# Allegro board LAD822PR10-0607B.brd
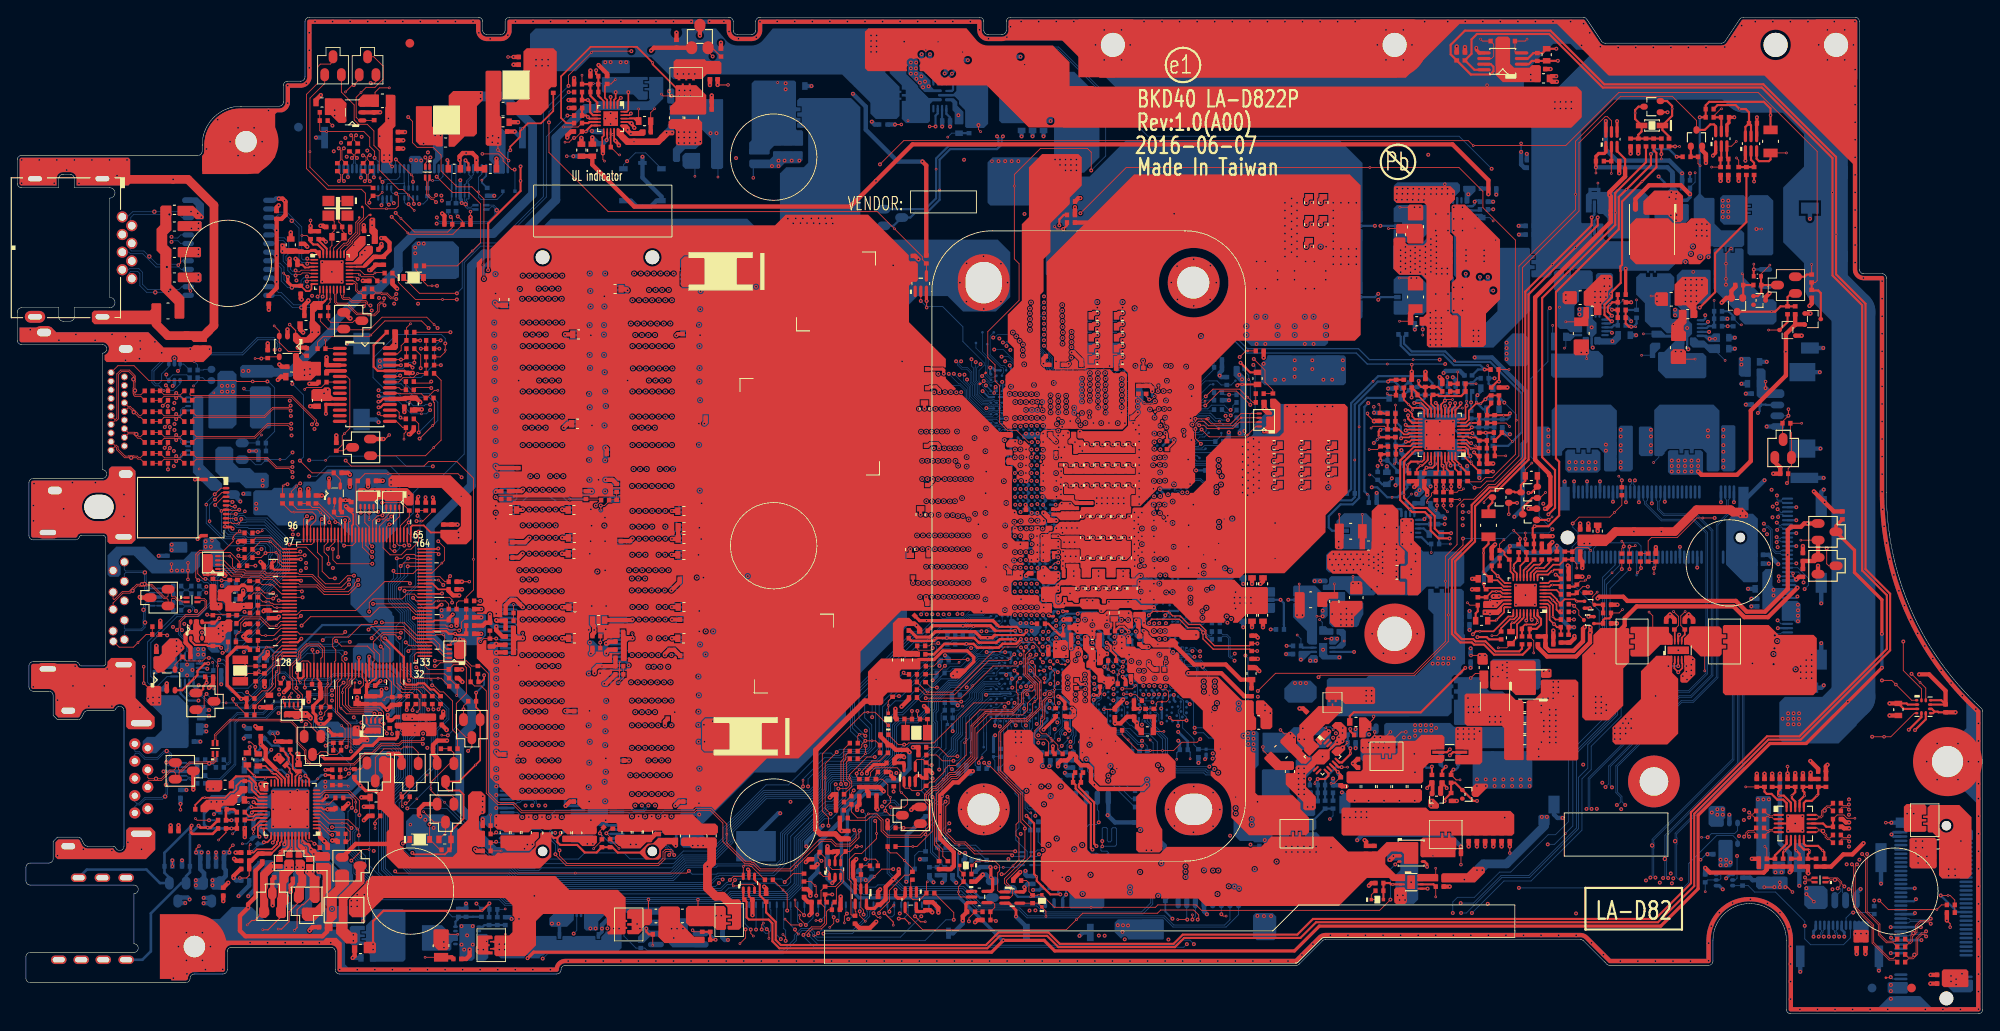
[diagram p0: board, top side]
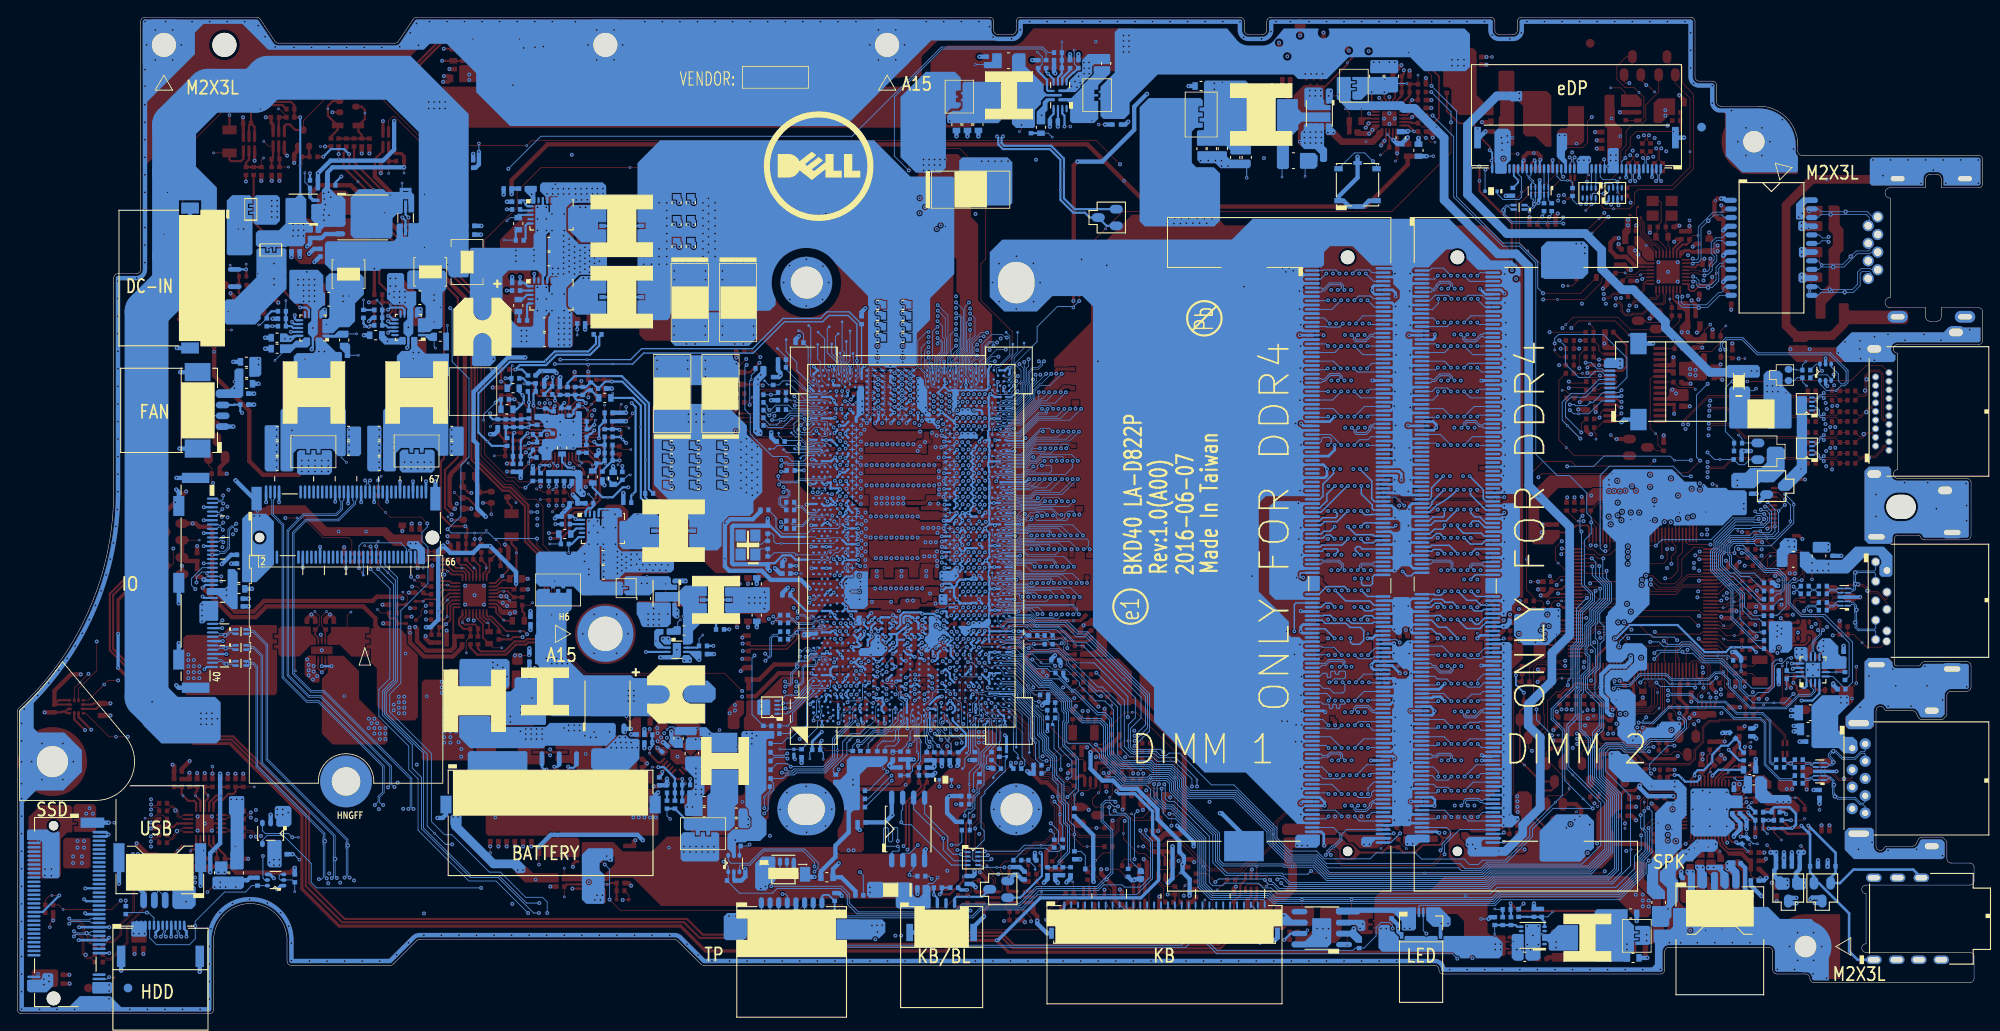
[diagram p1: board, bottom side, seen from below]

Outline 227.47 x 115.4 mm; copper layers: TOP, GND1, IN1, VCC, IN2, IN3, GND2, BOTTOM. Coordinates in mm from the lower left corner of the outline.

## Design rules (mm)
constraint set DEFAULT: min track width 0.102, pair gap 0.127
net group CLK_ITPXDP: nets CLK_ITPXDP_N CLK_ITPXDP_P
net group CLK_PCIE_LAN_P2_R: nets CLK_PCIE_LAN_N2_R CLK_PCIE_LAN_P2_R
net group CLK_PCIE_WLAN_P1_R: nets CLK_PCIE_WLAN_N1_R CLK_PCIE_WLAN_P1_R
net group DIFFPAIR2: nets SATA3_PRX_C_SSDTX_N2 SATA3_PRX_C_SSDTX_P2
net group DIFFPAIR3: nets SATA3_PTX_C_SSDRX_N2 SATA3_PTX_C_SSDRX_P2
net group DIFFPAIR4: nets PBAT_CHG_SMBCLK PBAT_CHG_SMBDAT
net group EDP_AUX_DP: nets EDP_AUX_DN EDP_AUX_DP
net group EDP_TX0_DP: nets EDP_TX0_DN EDP_TX0_DP
net group EDP_TX1_DP: nets EDP_TX1_DN EDP_TX1_DP
net group LAN_MIDI1+: nets LAN_MIDI1+ LAN_MIDI1-
net group LAN_MIDI3+: nets LAN_MIDI3+ LAN_MIDI3-
net group PCIE_PRX_C_LANTX_P6: nets PCIE_PRX_C_LANTX_N6 PCIE_PRX_C_LANTX_P6
net group PCIE_PRX_LANTX_P6: nets PCIE_PRX_LANTX_N6 PCIE_PRX_LANTX_P6
net group PCIE_PRX_WLANTX_P5: nets PCIE_PRX_WLANTX_N5 PCIE_PRX_WLANTX_P5
net group PCIE_PTX_C_LANRX_P6: nets PCIE_PTX_C_LANRX_N6 PCIE_PTX_C_LANRX_P6
net group PCIE_PTX_LANRX_P6: nets PCIE_PTX_LANRX_N6 PCIE_PTX_LANRX_P6
net group PCIE_PTX_WLANRX_P5: nets PCIE_PTX_WLANRX_N5 PCIE_PTX_WLANRX_P5
net group PCIE_RCOMPP: nets PCIE_RCOMPN PCIE_RCOMPP
net group SDOV_SCLK: nets SDVO_SCLK SDVO_SDATA
net group USB_PP1: nets USB_PN1 USB_PP1
net group AUDIO: nets AUD_HP_OUT_L_CN AUD_HP_OUT_R_CN HPOUT-L HPOUT-R LINE1-L LINE1-R LINE1-VREFO-L LINE1-VREFO-R LINE-IN-L LINE-IN-R
net group DDR_A_CLK: nets DDR_A_CLK0 DDR_A_CLK1 DDR_A_CLK#0 DDR_A_CLK#1
net group DDR_A_CMD: nets DDR_A_ACT# DDR_A_ALERT# DDR_A_BG0 DDR_A_BG1 DDR_A_BS0 DDR_A_BS1 DDR_A_CAS# DDR_A_MA0 DDR_A_MA1 DDR_A_MA2 DDR_A_MA3 DDR_A_MA4 DDR_A_MA5 DDR_A_MA6 DDR_A_MA7 DDR_A_MA8 DDR_A_MA9 DDR_A_MA10 DDR_A_MA11 DDR_A_MA12 DDR_A_MA13 DDR_A_PAR DDR_A_RAS# DDR_A_WE#
net group DDR_A_CTL: nets DDR_A_CKE0 DDR_A_CKE1 DDR_A_CS#0 DDR_A_CS#1 DDR_A_ODT0 DDR_A_ODT1
net group DDR_A_D0: nets DDR_A_D0 DDR_A_D1 DDR_A_D2 DDR_A_D3 DDR_A_D4 DDR_A_D5 DDR_A_D6 DDR_A_D7 DDR_A_DQS0 DDR_A_DQS#0
net group DDR_A_D1: nets DDR_A_D8 DDR_A_D9 DDR_A_D10 DDR_A_D11 DDR_A_D12 DDR_A_D13 DDR_A_D14 DDR_A_D15 DDR_A_DQS1 DDR_A_DQS#1
net group DDR_A_D2: nets DDR_A_D16 DDR_A_D17 DDR_A_D18 DDR_A_D19 DDR_A_D20 DDR_A_D21 DDR_A_D22 DDR_A_D23 DDR_A_DQS2 DDR_A_DQS#2
net group DDR_A_D3: nets DDR_A_D24 DDR_A_D25 DDR_A_D26 DDR_A_D27 DDR_A_D28 DDR_A_D29 DDR_A_D30 DDR_A_D31 DDR_A_DQS3 DDR_A_DQS#3
net group DDR_A_D4: nets DDR_A_D32 DDR_A_D33 DDR_A_D34 DDR_A_D35 DDR_A_D36 DDR_A_D37 DDR_A_D38 DDR_A_D39 DDR_A_DQS4 DDR_A_DQS#4
net group DDR_A_D5: nets DDR_A_D40 DDR_A_D41 DDR_A_D42 DDR_A_D43 DDR_A_D44 DDR_A_D45 DDR_A_D46 DDR_A_D47 DDR_A_DQS5 DDR_A_DQS#5
net group DDR_A_D6: nets DDR_A_D48 DDR_A_D49 DDR_A_D50 DDR_A_D51 DDR_A_D52 DDR_A_D53 DDR_A_D54 DDR_A_D55 DDR_A_DQS6 DDR_A_DQS#6
net group DDR_A_D7: nets DDR_A_D56 DDR_A_D57 DDR_A_D58 DDR_A_D59 DDR_A_D60 DDR_A_D61 DDR_A_D62 DDR_A_D63 DDR_A_DQS7 DDR_A_DQS#7
net group DDR_B_CLK: nets DDR_B_CLK0 DDR_B_CLK1 DDR_B_CLK#0 DDR_B_CLK#1
net group DDR_B_CMD: nets DDR_B_ACT# DDR_B_ALERT# DDR_B_BG0 DDR_B_BG1 DDR_B_BS0 DDR_B_BS1 DDR_B_CAS# DDR_B_MA0 DDR_B_MA1 DDR_B_MA2 DDR_B_MA3 DDR_B_MA4 DDR_B_MA5 DDR_B_MA6 DDR_B_MA7 DDR_B_MA8 DDR_B_MA9 DDR_B_MA10 DDR_B_MA11 DDR_B_MA12 DDR_B_MA13 DDR_B_PAR DDR_B_RAS# DDR_B_WE#
net group DDR_B_CTL: nets DDR_B_CKE0 DDR_B_CKE1 DDR_B_CS#0 DDR_B_CS#1 DDR_B_ODT0 DDR_B_ODT1
net group DDR_B_D0: nets DDR_B_D0 DDR_B_D1 DDR_B_D2 DDR_B_D3 DDR_B_D4 DDR_B_D5 DDR_B_D6 DDR_B_D7 DDR_B_DQS0 DDR_B_DQS#0
net group DDR_B_D1: nets DDR_B_D8 DDR_B_D9 DDR_B_D10 DDR_B_D11 DDR_B_D12 DDR_B_D13 DDR_B_D14 DDR_B_D15 DDR_B_DQS1 DDR_B_DQS#1
net group DDR_B_D2: nets DDR_B_D16 DDR_B_D17 DDR_B_D18 DDR_B_D19 DDR_B_D20 DDR_B_D21 DDR_B_D22 DDR_B_D23 DDR_B_DQS2 DDR_B_DQS#2
net group DDR_B_D3: nets DDR_B_D24 DDR_B_D25 DDR_B_D26 DDR_B_D27 DDR_B_D28 DDR_B_D29 DDR_B_D30 DDR_B_D31 DDR_B_DQS3 DDR_B_DQS#3
net group DDR_B_D4: nets DDR_B_D32 DDR_B_D33 DDR_B_D34 DDR_B_D35 DDR_B_D36 DDR_B_D37 DDR_B_D38 DDR_B_D39 DDR_B_DQS4 DDR_B_DQS#4
net group DDR_B_D5: nets DDR_B_D40 DDR_B_D41 DDR_B_D42 DDR_B_D43 DDR_B_D44 DDR_B_D45 DDR_B_D46 DDR_B_D47 DDR_B_DQS5 DDR_B_DQS#5
net group DDR_B_D6: nets DDR_B_D48 DDR_B_D49 DDR_B_D50 DDR_B_D51 DDR_B_D52 DDR_B_D53 DDR_B_D54 DDR_B_D55 DDR_B_DQS6 DDR_B_DQS#6
net group DDR_B_D7: nets DDR_B_D56 DDR_B_D57 DDR_B_D58 DDR_B_D59 DDR_B_D60 DDR_B_D61 DDR_B_D62 DDR_B_D63 DDR_B_DQS7 DDR_B_DQS#7
net group HDA: nets HDA_BIT_CLK HDA_CODEC_BITCLK HDA_CODEC_RST# HDA_CODEC_SDIN0 HDA_CODEC_SDOUT HDA_CODEC_SYNC HDA_RST# HDA_SDIN0 HDA_SDOUT HDA_SYNC ME_FWP_EC
net group KBO: nets KSI0 KSI1 KSI2 KSI3 KSI4 KSI5 KSI6 KSI7 KSO0 KSO1 KSO2 KSO3 KSO4 KSO5 KSO6 KSO7 KSO8 KSO9 KSO10 KSO11 KSO12 KSO13 KSO14 KSO15
net group PCIE: nets PCIE_PTX_C_WLANRX_N5 PCIE_PTX_C_WLANRX_P5 PCIE_WAKE#
net group S-8: nets LAN_WAKE# SERIRQ SYS_PWROK SYS_RESET#
net group SATA: nets SATA3_PRX_HDDTX_P0 SATA3_PRX_SSDTX_N2 SATA3_PRX_SSDTX_P2 SATA3_PTX_SSDRX_N2 SATA3_PTX_SSDRX_P2
net group SPI: nets EC_SPI_CLK EC_SPI_CS0# EC_SPI_MISO EC_SPI_MOSI EC_SPICLK_R EC_SPICS#_R PCH_SPI1_CLK_R PCH_SPI_CLK PCH_SPI_CLK_R PCH_SPI_CS2# PCH_SPI_CS2#_R PCH_SPI_CS#0 PCH_SPI_D0 PCH_SPI_D0_R PCH_SPI_D1 PCH_SPI_D1_R PCH_SPI_D2 PCH_SPI_D2_R PCH_SPI_D3 PCH_SPI_D3_R PCH_SPI_MISO PCH_SPI_MOSI XDP_SPI_IO2
net group SPK: nets INT-SPK-L+ INT-SPK-L- INT-SPK-R+ INT-SPK-R- MIC_IN_R RING2 RING2_R SLEEVE SPK_L1-_CONN SPK_L2+_CONN SPK_R1-_CONN SPK_R2+_CONN
net group USB_PP1_CHR: nets USB_PN1_CHR
nets with their own width: min track width 0.127; nets +TP_VDD
nets with their own width: min track width 0.152; nets VCC_GT_SENSE VCCSENSE VSA_SEN+ VSA_SEN- VSS_GT_SENSE VSSSENSE
nets with their own width: min track width 0.254; nets BAT1_LED# BAT2_LED# CFG_RCOMP CLK_SMB DAT_SMB EDP_COMP EN_1.0V_VCCST_ON KB_BL_CTRL# KB_LED_BL_DET KB_LED_DET_C KB_LED_PWM LDO_+1VALW N40605947 N41378522 N41825015 SM_RCOMP0 SM_RCOMP1 SM_RCOMP2
nets with their own width: min track width 0.305; nets CBN CBP CPU_POPIRCOMP CPVEE
nets with their own width: min track width 0.381; nets LDO3_CAP
nets with their own width: min track width 0.508; nets +1.0VS_VCCIO +1.0VS_VCCOPC +1.8V_AVDD +1.8V_PRIM +1.8VALWP +3V_SPI +3VALW +3VALW_PCH +3VS +5VALW +5VS +VCC_GT BST_+1VALW_R GND GNDA N28714793 N41866816
nets with their own width: min track width 0.762; nets +3.3V_LAN
nets with their own width: min track width 1.016; nets +0.6V_DDR_VTT +1.0V_PRIM +1.0V_VCCST +2.5V_MEM +2.5VP +3.3V_WLAN +DCBATOUT_LCD +TPAN_VDD LAN_GND MCT1 MCT2 MCT3 MCT4 N40740280
nets with their own width: min track width 1.27; nets 5V_HDD
nets with their own width: min track width 1.524; nets +0.6VSP +LAN_VDDREG
nets with their own width: min track width 2.032; nets +5V_PVDD +5VS_HDMI +LCDVDD_LCD +USB30_VCCB +USB30_VCCC
nets with their own width: min track width 2.54; nets +USB30_VCCA
nets with their own width: min track width 4.064; nets +3VS_SSD

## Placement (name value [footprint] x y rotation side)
C229  VALUE}  [C_0402]  29.11 82.23 90 top
C2403  VALUE}  [C_0402]  25.48 50.24 270 top
C2503  VALUE}  [C_0402]  211.23 57.26 90 top
C2601  VALUE}  [C_0603]  175.92 108.33 0 top
C2602  VALUE}  [C_0402]  175.91 109.41 0 top
C2603  VALUE}  [C_0402]  201.65 71.81 180 bottom
C2604  VALUE}  [C_0402]  200.74 70.54 0 bottom
C2606  VALUE}  [C_0603]  177 110.36 90 top
C2607  VALUE}  [C_0402]  175.92 110.35 90 top
C2608  VALUE}  [C_0402]  167.54 110.41 90 top
C2609  VALUE}  [C_0402]  166.59 110.41 90 top
C2612  VALUE}  [C_0402]  123.1 26.79 180 top
C2613  VALUE}  [C_0402]  47.15 33.46 90 top
C2715  VALUE}  [C_0402]  26.84 17.71 180 top
C3013  VALUE}  [C_0402]  32.17 74.93 180 top
C3015  VALUE}  [C_0402]  34.14 80.83 180 top
C3017  VALUE}  [C_0402]  33.49 77.99 270 top
C3403  VALUE}  [C_0402]  21.06 48.64 180 bottom
C3404  VALUE}  [C_0402]  21.06 49.53 180 bottom
C3405  VALUE}  [C_0402]  23.9 29.42 180 bottom
C3406  VALUE}  [C_0402]  23.9 28.53 180 bottom
C3504  VALUE}  [C_0402]  16.09 41 90 top
C3507  VALUE}  [C_0402]  19.52 31.52 0 bottom
C3508  VALUE}  [C_0402]  17.36 52.12 90 bottom
C3510  VALUE}  [C_0402]  197.21 18.47 180 bottom
C3512  VALUE}  [C_0805]  18.95 52.17 90 bottom
C3513  VALUE}  [C_0805]  19.37 32.95 0 bottom
C5201  VALUE}  [C_0402]  43.13 100.2 0 top
C5202  VALUE}  [C_0402]  55.77 102.17 0 top
C5203  VALUE}  [C_0402]  38.45 100.78 270 top
C5204  VALUE}  [C_0603]  35.97 105.53 180 top
C5205  VALUE}  [C_0603]  56.92 103.25 180 top
C5206  VALUE}  [C_0402]  44.05 101.15 180 top
C5207  VALUE}  [C_0603]  51.27 97.85 180 top
C5209  VALUE}  [C_0402]  40.03 98.5 270 top
C5210  VALUE}  [C_0402]  39.4 100.78 270 top
C5211  VALUE}  [C_0402]  37.05 98.5 270 top
C5212  VALUE}  [C_0402]  40.99 98.5 270 top
C5213  VALUE}  [C_0402]  38 98.5 270 top
C5224  VALUE}  [C_0603]  39.34 37.33 270 top
C5225  VALUE}  [C_0402]  28.6 40.27 90 top
C5226  VALUE}  [C_0402]  28.6 39.4 270 top
C5529  VALUE}  [C_0402]  223.12 4.5 180 top
C5530  VALUE}  [C_0402]  222.74 17.33 180 top
C5531  VALUE}  [C_0402]  223.12 3.49 180 top
C5532  VALUE}  [C_0603]  223 19.62 180 top
C5533  VALUE}  [C_0402]  222.74 18.22 180 top
C5801  VALUE}  [C_0402]  202.29 48.06 180 bottom
C5802  VALUE}  [C_0402]  202.29 47.18 180 bottom
C5803  VALUE}  [C_0402]  180.88 55.16 90 top
C5804  VALUE}  [C_0402]  201.12 52.13 0 bottom
C5805  VALUE}  [C_0603]  202.53 49.21 180 bottom
C5806  VALUE}  [C_0603]  182.91 55.18 90 top
C6201  VALUE}  [C_0402]  132.87 13.06 90 bottom
C6202  VALUE}  [C_0402]  122.38 14.6 0 bottom
C6204  VALUE}  [C_0402]  48.11 30.69 0 top
C6213  VALUE}  [C_0603]  201.64 72.96 180 bottom
C6214  VALUE}  [C_0603]  200.24 75.5 0 bottom
C6215  VALUE}  [C_0402]  212.88 8.52 270 top
C6216  VALUE}  [C_0805]  203.86 15.46 90 bottom
C6217  VALUE}  [C_0402]  213.9 8.52 270 top
C6218  VALUE}  [C_0603]  29.18 35.49 90 top
C6219  VALUE}  [C_0402]  43.13 102.1 0 top
C6220  VALUE}  [C_0402]  16.55 44.83 180 top
C6221  VALUE}  [C_0402]  181.83 55.16 90 top
C6223  VALUE}  [C_0402]  38 19.92 180 top
C6225  VALUE}  [C_0402]  92.84 12.94 180 top
C6226  VALUE}  [C_0402]  94.28 12.05 0 top
CA23  VALUE}  [C_0603]  24.88 24.76 0 top
CA24  VALUE}  [C_0402]  27.85 19.67 135 bottom
CA25  VALUE}  [C_0402]  28.1 24.12 270 bottom
CA29  VALUE}  [C_0402]  28.95 17.43 180 bottom
CA30  VALUE}  [C_0402]  30.66 15.79 180 top
CA31  VALUE}  [C_0402]  33.81 15.73 0 bottom
CA32  VALUE}  [C_0402]  32.81 15.6 180 top
CA33  VALUE}  [C_0402]  17.03 17.08 0 bottom
CA38  VALUE}  [C_0402]  23.92 17.08 180 bottom
CA39  VALUE}  [C_0402]  19.98 17.08 180 bottom
CA40  VALUE}  [C_0402]  21.17 17.08 0 bottom
CA51  VALUE}  [C_0402]  26.97 25.93 180 bottom
CA53  VALUE}  [C_0402]  37.71 10.32 270 bottom
CA54  VALUE}  [C_0402]  35.77 17.99 270 top
CA55  VALUE}  [C_0402]  36.8 10.32 270 bottom
CA56  VALUE}  [C_0402]  34.85 17.99 270 top
CA57  VALUE}  [C_0603]  42.23 25.05 180 top
CA58  VALUE}  [C_0402]  41.99 23.97 180 top
CA59  VALUE}  [C_0402]  28.98 23.21 90 bottom
CA60  VALUE}  [C_0402]  28.06 21.76 0 bottom
CA61  VALUE}  [C_0402]  26.84 16.76 180 top
CA62  VALUE}  [C_0402]  26.33 26.04 90 top
CA63  VALUE}  [C_0402]  25.92 18.66 0 top
CA64  VALUE}  [C_0402]  37.74 23.79 180 top
CA65  VALUE}  [C_0402]  37.37 26.47 90 top
CA67  VALUE}  [C_0603]  26.63 28.82 90 top
CA68  VALUE}  [C_0603]  27.9 28.69 90 top
CA69  VALUE}  [C_0402]  36.58 31.38 90 top
CA71  VALUE}  [C_0603]  27.2 27.03 180 bottom
CA74  VALUE}  [C_0603]  27.68 28.25 180 bottom
CA75  VALUE}  [C_0402]  23.92 17.98 180 bottom
CA76  VALUE}  [C_0402]  21.17 17.99 0 bottom
CC9  VALUE}  [C_0402]  129.3 22.16 0 bottom
CC21  VALUE}  [C_0402]  140.62 55.61 90 bottom
CC22  VALUE}  [C_0402]  140.62 52.97 270 bottom
CC23  VALUE}  [C_0402]  105.33 34.12 90 top
CC24  VALUE}  [C_0402]  98.9 16.77 270 bottom
CC25  VALUE}  [C_0402]  99.61 28.01 0 top
CC26  VALUE}  [C_0402]  102.68 34.13 180 top
CC27  VALUE}  [C_0402]  109.43 43.81 0 bottom
CC57  VALUE}  [C_0402]  103.66 86.85 90 top
CC58  VALUE}  [C_0402]  142.76 35.02 0 top
CC59  VALUE}  [C_0402]  157.06 18.52 90 top
CC93  VALUE}  [C_0402]  110.43 15.3 180 top
CC135  VALUE}  [C_0402]  139.17 46.16 180 bottom
CC136  VALUE}  [C_0402]  139.17 45.27 180 bottom
CC174  VALUE}  [C_0402]  114.84 50.21 90 top
CC175  VALUE}  [C_0402]  105.18 66.68 270 top
CC176  VALUE}  [C_0402]  105.31 60.31 90 top
CC177  VALUE}  [C_0402]  104.41 47.49 0 top
CC178  VALUE}  [C_0402]  103.66 51.44 270 top
CC179  VALUE}  [C_0402]  104.54 53.12 0 top
CC181  VALUE}  [C_0402]  119.8 50.02 270 top
CC182  VALUE}  [C_0402]  119.5 57.12 270 top
CC185  VALUE}  [C_0402]  118.28 51.01 180 top
CC186  VALUE}  [C_0402]  172.74 20.91 270 top
CC194  VALUE}  [C_0402]  114.81 63.05 90 top
CC195  VALUE}  [C_0402]  130.34 46.15 90 top
CC199  VALUE}  [C_0402]  138 48.47 0 bottom
CC202  VALUE}  [C_0402]  129.46 46.15 90 top
CC203  VALUE}  [C_0402]  129.25 34.4 90 top
CC204  VALUE}  [C_0402]  118.58 30.27 270 bottom
CC205  VALUE}  [C_0402]  123.94 46.21 90 top
CC206  VALUE}  [C_0402]  128.01 46.34 90 top
CC207  VALUE}  [C_0402]  91.98 16.99 90 top
CC210  VALUE}  [C_0805]  142.83 33.73 0 top
CC211  VALUE}  [C_0402]  128.68 42.17 90 top
CC212  VALUE}  [C_0402]  123.08 40.38 0 top
CC213  VALUE}  [C_0402]  107.8 40.95 180 bottom
CC214  VALUE}  [C_0402]  109.08 36.93 180 bottom
CC215  VALUE}  [C_0402]  121.05 43.86 0 top
CC216  VALUE}  [C_0402]  121.85 44.75 90 top
CC217  VALUE}  [C_0402]  142.76 35.91 0 top
CC218  VALUE}  [C_0402]  128.87 40.01 270 top
CC220  VALUE}  [C_0603]  142.84 38.69 90 top
CC221  VALUE}  [C_0402]  129.89 43.72 270 top
CC223  VALUE}  [C_0402]  120.25 41.65 180 top
CC224  VALUE}  [C_0402]  121.05 42.96 0 top
CC225  VALUE}  [C_0603]  125.12 42.79 180 top
CC226  VALUE}  [C_0603]  126.97 45.71 90 top
CC248  VALUE}  [C_0402]  171.78 20.91 270 top
CC249  VALUE}  [C_0402]  170.83 20.91 270 top
CC250  VALUE}  [C_0402]  169.88 20.91 270 top
CC251  VALUE}  [C_0402]  168.93 20.91 270 top
CC252  VALUE}  [C_0402]  167.97 20.91 270 top
CC253  VALUE}  [C_0402]  118.91 50.02 270 top
CC255  VALUE}  [C_0402]  105.31 75.57 270 top
CC256  VALUE}  [C_0402]  116.74 54.35 90 top
CC257  VALUE}  [C_0402]  114.84 65.01 90 top
CC258  VALUE}  [C_0402]  105.31 73.35 270 top
CC265  VALUE}  [C_0402]  91.06 14.43 270 top
CC266  VALUE}  [C_0402]  97.64 16.12 180 top
CC270  VALUE}  [C_0402]  98.52 25.24 0 top
CC271  VALUE}  [C_0402]  99.62 12.63 90 top
CC272  VALUE}  [C_0402]  122.34 33.59 180 top
CC273  VALUE}  [C_0402]  124.83 46.21 90 top
CC279  VALUE}  [C_0603]  101.82 40.25 90 top
CC280  VALUE}  [C_0603]  103.09 40.25 90 top
CC293  VALUE}  [C_0603]  103.34 54.48 270 top
CC294  VALUE}  [C_0603]  104.55 57.08 90 top
CC295  VALUE}  [C_0603]  104.99 69.34 90 top
CC296  VALUE}  [C_0402]  116.73 57.44 90 top
CC297  VALUE}  [C_0402]  119.47 47.23 90 top
CC1801  VALUE}  [C_0402]  125.25 40.64 270 top
CC1802  VALUE}  [C_0402]  108.26 36.04 180 bottom
CC1803  VALUE}  [C_0201]  108.23 33.5 180 bottom
CC1805  VALUE}  [C_0402]  50.88 38.87 180 top
CC1806  VALUE}  [C_0402]  105.18 26.4 90 top
CC1807  VALUE}  [C_0201]  137.59 30.63 270 bottom
CC1808  VALUE}  [C_0402]  138.51 71.05 0 bottom
CC1809  VALUE}  [C_0402]  143.34 70.8 0 top
CC1810  VALUE}  [C_0402]  32.73 59.1 90 top
CC1815  VALUE}  [C_0402]  139.17 44.25 180 bottom
CC1816  VALUE}  [C_0402]  139.17 43.37 180 bottom
CC1820  VALUE}  [C_0402]  105.12 12 90 top
CC1821  VALUE}  [C_0402]  110.9 16.45 270 bottom
CC1822  VALUE}  [C_0402]  110.85 11.81 180 top
CC1823  VALUE}  [C_0201]  112.98 30.36 270 bottom
CC1824  VALUE}  [C_0402]  121.5 94.06 0 top
CC1825  VALUE}  [C_0402]  127.18 73.79 90 top
CC1826  VALUE}  [C_0402]  128.13 69.01 0 top
CC1827  VALUE}  [C_0402]  122.23 68.02 270 top
CC1828  VALUE}  [C_0402]  119.54 68.02 270 top
CC1829  VALUE}  [C_0402]  118.13 76.14 0 top
CC1830  VALUE}  [C_0402]  119.43 74.24 90 top
CC1831  VALUE}  [C_0402]  121.03 74.24 90 top
CC1832  VALUE}  [C_0402]  123.14 74.24 90 top
CD1  VALUE}  [C_0402]  69.27 29.32 0 top
CD2  VALUE}  [C_0402]  67.31 64.83 0 top
CD3  VALUE}  [C_0402]  79.28 20.18 90 top
CD4  VALUE}  [C_0402]  65.88 20.3 90 top
CD5  VALUE}  [C_0603]  77.85 58.21 180 top
CD6  VALUE}  [C_0603]  56.39 58.34 0 top
CD7  VALUE}  [C_0603]  65.21 43.48 180 top
CD8  VALUE}  [C_0603]  65.15 53.26 180 top
CD9  VALUE}  [C_0603]  80.36 19.87 90 top
CD10  VALUE}  [C_0603]  63.53 20.25 90 top
CD11  VALUE}  [C_D3]  87.49 32.13 180 top
CD12  VALUE}  [C_0402]  74.2 20.81 90 top
CD13  VALUE}  [C_0603]  70.51 20.32 90 top
CD14  VALUE}  [C_0603]  58.96 20.27 90 top
CD15  VALUE}  [C_0603]  57.69 20.27 90 top
CD16  VALUE}  [C_0402]  76.2 20.14 90 top
CD17  VALUE}  [C_0603]  66.58 45.59 0 top
CD18  VALUE}  [C_0402]  70.15 43.11 180 top
CD19  VALUE}  [C_0402]  56.39 52.83 0 top
CD20  VALUE}  [C_0402]  76.19 34.16 180 top
CD21  VALUE}  [C_0402]  78.01 24.57 180 top
CD22  VALUE}  [C_0402]  77.64 41.46 180 top
CD23  VALUE}  [C_0603]  77.88 54.99 180 top
CD24  VALUE}  [C_0603]  65.15 58.34 180 top
CD25  VALUE}  [C_0603]  68.48 83.94 0 top
CD26  VALUE}  [C_0603]  65.2 55.1 180 top
CD27  VALUE}  [C_0603]  64.8 20.25 90 top
CD28  VALUE}  [C_0603]  77.28 19.86 90 top
CD29  VALUE}  [C_0402]  57.43 41.84 180 top
CD30  VALUE}  [C_0402]  66.77 20.3 90 top
CD31  VALUE}  [C_0402]  78.36 20.16 90 top
CD32  VALUE}  [C_0402]  60.04 20.75 90 top
CD33  VALUE}  [C_D3]  84.6 85.97 180 top
CD34  VALUE}  [C_0402]  75.28 20.11 90 top
CD35  VALUE}  [C_0603]  61.36 20.23 90 top
CD69  VALUE}  [C_0402]  56.01 59.6 90 top
CD70  VALUE}  [C_0603]  77.89 47.1 180 top
CD71  VALUE}  [C_0603]  65.56 68.32 180 top
CD72  VALUE}  [C_0603]  77.88 56.38 180 top
CD73  VALUE}  [C_0603]  65.69 78.67 180 top
CD74  VALUE}  [C_0402]  78.76 69.02 0 top
CD75  VALUE}  [C_0402]  68.91 54.73 0 top
CD76  VALUE}  [C_0402]  77.58 50.35 180 top
CD77  VALUE}  [C_0402]  65.4 35.05 180 top
CD78  VALUE}  [C_0402]  65.33 24.57 180 top
CD79  VALUE}  [C_0402]  57.28 30.03 180 top
CD80  VALUE}  [C_0402]  56.33 54.61 0 top
CD81  VALUE}  [C_0402]  77.64 45.65 180 top
CD82  VALUE}  [C_0402]  77.93 78.72 180 top
CD83  VALUE}  [C_0402]  57.99 62.28 90 top
CD84  VALUE}  [C_0603]  65.24 47.08 180 top
CD85  VALUE}  [C_0603]  77.85 53.13 180 top
CD86  VALUE}  [C_0603]  77.85 43.48 180 top
CD87  VALUE}  [C_0603]  56.35 83.43 270 top
CD88  VALUE}  [C_0603]  71.78 20.32 90 top
CD89  VALUE}  [C_0603]  56.42 20.27 90 top
CD90  VALUE}  [C_0603]  72.99 20.32 90 top
CD91  VALUE}  [C_0402]  65.81 59.61 90 top
CD92  VALUE}  [C_0402]  56.92 59.61 90 top
CE1  VALUE}  [C_0402]  76.29 111.87 90 top
CE2  VALUE}  [C_0402]  81.44 110.85 90 top
CE8  VALUE}  [C_0402]  51.96 46.86 0 top
CE62  VALUE}  [C_0402]  50.26 55.74 90 top
CE63  VALUE}  [C_0402]  49.3 56.65 270 top
CE64  VALUE}  [C_0402]  29.15 45.8 90 top
CE65  VALUE}  [C_0402]  40.41 36.78 270 top
CE66  VALUE}  [C_0402]  49.93 49.14 0 top
CE67  VALUE}  [C_0402]  29.45 51.72 180 top
CE68  VALUE}  [C_0402]  38.64 58.34 90 top
CE69  VALUE}  [C_0402]  49.93 45.59 0 top
CE70  VALUE}  [C_0402]  25.4 46.17 90 top
CE71  VALUE}  [C_0402]  41.37 36.78 270 top
CE72  VALUE}  [C_0402]  49.93 50.03 0 top
CE73  VALUE}  [C_0402]  27.85 43.24 180 top
CE74  VALUE}  [C_0402]  48.16 58.28 90 top
CE75  VALUE}  [C_0402]  51.96 44 0 top
CE76  VALUE}  [C_0402]  27.22 54.73 180 top
CE77  VALUE}  [C_0402]  127.03 34.34 90 top
CE79  VALUE}  [C_0402]  40.5 38.01 0 top
CE81  VALUE}  [C_0402]  22.55 48.19 0 top
CE82  VALUE}  [C_0402]  46.32 58.28 90 top
CE84  VALUE}  [C_0402]  31.4 38.29 180 top
CE85  VALUE}  [C_0402]  40.59 61.72 0 top
CE86  VALUE}  [C_0402]  36.62 62.64 0 top
CE87  VALUE}  [C_0402]  26.89 50.11 270 top
CE88  VALUE}  [C_0402]  27.85 47.3 180 top
CE89  VALUE}  [C_0603]  35.12 36.99 180 top
CE91  VALUE}  [C_0402]  43.4 36.67 270 top
CH100  VALUE}  [C_0402]  56.52 45.53 0 top
CH101  VALUE}  [C_0402]  69.23 40.25 0 top
CHD1  VALUE}  [C_0402]  217.58 8.64 0 top
CHD2  VALUE}  [C_0402]  217.58 7.75 0 top
CHD3  VALUE}  [C_0402]  217.58 6.87 0 top
CHD4  VALUE}  [C_0402]  217.58 5.98 0 top
CHO8  VALUE}  [C_0402]  16.53 68.6 0 top
CHO9  VALUE}  [C_0402]  16.53 71.04 0 top
CHO10  VALUE}  [C_0402]  16.53 66.16 0 top
CHO11  VALUE}  [C_0402]  16.53 63.75 0 top
CHR7  VALUE}  [C_0402]  20.25 63.75 180 top
CHR8  VALUE}  [C_0402]  20.25 64.89 180 top
CHR9  VALUE}  [C_0402]  20.25 66.16 180 top
CHR10  VALUE}  [C_0402]  20.25 67.3 180 top
CHR11  VALUE}  [C_0402]  20.25 71.05 180 top
CHR12  VALUE}  [C_0402]  20.25 72.13 180 top
CHR13  VALUE}  [C_0402]  20.25 68.57 180 top
CHR14  VALUE}  [C_0402]  20.25 69.72 180 top
CL1  VALUE}  [C_0402]  40.88 88.51 0 top
CL2  VALUE}  [C_0402]  42.41 87.65 270 top
CL3  VALUE}  [C_0402]  32.86 88.25 90 top
CL4  VALUE}  [C_0402]  41.47 87.65 270 top
CL5  VALUE}  [C_0603]  31.65 88.32 90 top
CL6  VALUE}  [C_0402]  32.8 84.3 270 top
CL7  VALUE}  [C_0402]  32.43 86.74 180 top
CL8  VALUE}  [C_0603]  34.13 79.75 180 top
CL9  VALUE}  [C_0402]  41.06 90.67 180 top
CL11  VALUE}  [C_0402]  34.14 81.78 180 top
CL12  VALUE}  [C_0402]  34.89 89.71 90 top
CL13  VALUE}  [C_0402]  40.15 83.05 0 top
CL14  VALUE}  [C_0402]  40.15 83.94 0 top
CL16  VALUE}  [C_0402]  37.61 91.12 0 top
CL17  VALUE}  [C_0402]  36.68 91.12 180 top
CL43  VALUE}  [C_1206]  18.76 81.39 180 top
CL44  VALUE}  [C_0402]  20.7 77.15 90 top
CL45  VALUE}  [C_0402]  21.61 77.15 90 top
CL46  VALUE}  [C_0402]  30.01 92.96 270 top
CLRP1  VALUE}  [SHORTPADS]  97.44 16.06 90 bottom
CN19  VALUE}  [C_0402]  223.17 35.82 270 top
CN20  VALUE}  [C_0603]  217.71 35.94 270 top
CS27  VALUE}  [C_0402]  202.48 17.05 180 top
CS30  VALUE}  [C_0402]  210.14 24.38 0 top
CS31  VALUE}  [C_0402]  210.14 20.7 0 top
CS32  VALUE}  [C_0402]  210.14 23.49 0 top
CS33  VALUE}  [C_0402]  201.25 21.52 0 top
CS34  VALUE}  [C_0402]  210.14 19.81 0 top
CS35  VALUE}  [C_0402]  201.25 20.57 0 top
CS36  VALUE}  [C_0402]  201.25 22.54 0 top
CS37  VALUE}  [C_0402]  201.25 23.49 0 top
CS42  VALUE}  [C_0402]  209.34 28.06 180 top
CUS20  VALUE}  [C_0402]  16.09 41 90 bottom
CZ23  VALUE}  [C_0402]  192.99 44.5 90 top
CZ44  VALUE}  [C_0402]  190.83 44.5 90 top
CZ45  VALUE}  [C_0402]  191.79 44.5 90 top
CZ50  VALUE}  [C_0402]  193.95 44.5 90 top
CZ70  VALUE}  [C_0402]  164.16 14.73 0 top
CZ87  VALUE}  [C_0402]  156.11 18.52 90 top
CZ92  VALUE}  [C_0402]  45.05 74.21 90 top
CZ93  VALUE}  [C_0603]  45.88 71.31 270 top
CZ94  VALUE}  [C_0402]  44.8 71.22 270 top
CZ95  VALUE}  [C_0402]  34.88 75.18 0 top
CZ96  VALUE}  [C_0603]  32.48 73.78 180 top
CZ97  VALUE}  [C_0603]  34.7 71.75 270 top
CZ98  VALUE}  [C_0201]  35.72 71.15 270 top
CZ1702  VALUE}  [C_0402]  116.18 15.43 180 top
CZ1705  VALUE}  [C_0402]  158.11 15.13 180 top
D2501  VALUE}  [BAS40-04_SOT23-3]  210.49 55.81 90 top
D3801  VALUE}  [RB551V-30_SOD323-2]  45.42 20.19 0 top
D5201  VALUE}  [BAT54C-7-F_SOT23-3]  40.54 110.83 180 top
D5202  VALUE}  [BAT54C-7-F_SOT23-3]  36.54 110.83 180 top
D5203  VALUE}  [RB551V-30_SOD323-2]  44.71 85.26 0 top
D5204  VALUE}  [RB551V-30_SOD323-2]  28.22 72.1 90 bottom
DA8  VALUE}  [BAT54C-7-F_SOT23-3]  34.17 30.03 0 top
DA10  VALUE}  [AZ5125-02SPR7G_SOT23-3]  18.57 13.05 180 bottom
DA12  VALUE}  [AZ5123-02SPR7G_SOT23-3]  22.51 13.05 180 bottom
DA13  VALUE}  [AZ5125-02SPR7G_SOT23-3]  29.52 13.95 180 top
DA14  VALUE}  [AZ5125-02SPR7G_SOT23-3]  33.49 11.51 0 top
DX4  VALUE}  [BAW56W_SOT323-3]  24.07 73.97 270 bottom
DZ3  VALUE}  [RB751S40T1G_SOD523-2]  120.76 27.11 180 bottom
DZ4  VALUE}  [RB751S40T1G_SOD523-2]  100.8 33.4 90 top
DZ1701  VALUE}  [RB751S40T1G_SOD523-2]  118.58 12.38 90 top
DZ1702  VALUE}  [RB751S40T1G_SOD523-2]  110.48 17.18 180 top
DZ1703  VALUE}  [RB751S40T1G_SOD523-2]  156.71 13.22 0 top
DZ1704  VALUE}  [RB751S40T1G_SOD523-2]  56.2 95.26 0 bottom
EC5205  VALUE}  [C_0402]  51.54 91.4 0 top
EC5206  VALUE}  [C_0402]  50.35 91.42 180 top
EC5210  VALUE}  [C_0402]  53.13 97.85 180 top
EC9701  VALUE}  [C_0402]  100.74 103.89 270 bottom
EC9702  VALUE}  [C_0402]  99.72 103.89 270 bottom
EC9703  VALUE}  [C_0402]  191.47 88.58 0 bottom
EC9706  VALUE}  [C_0402]  175.62 97.98 180 bottom
EC9707  VALUE}  [C_0402]  167.16 45.09 0 bottom
EC9708  VALUE}  [C_0402]  191.47 87.69 0 bottom
EC9709  VALUE}  [C_0402]  175.62 98.86 180 bottom
EC9710  VALUE}  [C_0402]  167.16 45.98 0 bottom
EC9711  VALUE}  [C_0402]  167.29 41.68 0 bottom
EC9712  VALUE}  [C_0402]  167.29 40.76 0 bottom
EC9716  VALUE}  [C_0402]  58.96 110.8 180 top
EC9749  VALUE}  [C_0402]  58.96 109.91 180 top
EC9750  VALUE}  [C_0402]  175.49 90.23 180 bottom
EC9751  VALUE}  [C_0402]  175.49 91.24 180 bottom
EC9752  VALUE}  [C_0402]  80.17 109.14 270 top
EC9753  VALUE}  [C_0402]  81.05 109.14 270 top
EU3403  VALUE}  [AZC199-02SPR7G_SOT23-3]  15.37 48.19 270 top
EU3404  VALUE}  [AZC199-02SPR7G_SOT23-3]  20.37 28.13 90 top
EU3405  VALUE}  [L05ESDL5V0NA-4_SLP2510P8-10-9]  50.27 95.75 180 bottom
F5201  VALUE}  [F_SMD1812P110TF-24]  60.34 107.56 180 top
F5203  VALUE}  [F_SMD1812P110TF-24]  52.3 103.5 180 top
F6201  VALUE}  [F_NANOSMDC050F-13P2-2]  124.89 14.35 0 bottom
F6202  VALUE}  [F_SMD1812P110TF-24]  23.06 69.46 0 bottom
FD1  VALUE}  [FIDUCIAL_C40M80]  219.23 2.98 0 top
FD2  VALUE}  [FIDUCIAL_C40M80]  214.66 2.98 180 bottom
FD3  VALUE}  [FIDUCIAL_C40M80]  45.43 112.39 0 top
FD4  VALUE}  [FIDUCIAL_C40M80]  32.54 102.67 180 bottom
H1  VALUE}  [H_2P8-G]  210.5 112.2 0 top
H3  VALUE}  [H_2P8-G]  159.41 112.2 0 top
H4  VALUE}  [H_2P8-G]  126.8 112.2 0 top
H5  VALUE}  [H_2P5-G]  26.48 100.99 0 top
H6  VALUE}  [H_4P0-G]  159.41 44 0 top
H7  VALUE}  [H_2P5-G]  20.5 7.78 0 top
H8  VALUE}  [H_3P6-G]  223.4 29.2 0 top
H9  VALUE}  [H_3P4X2P8N]  9.45 58.7 0 top
H10  VALUE}  [H_2P8N]  203.5 112.2 0 top
HCPU1  VALUE}  [H_4P2X4P8]  111.85 84.67 0 top
HCPU2  VALUE}  [H_3P7]  136.1 84.67 0 top
HCPU3  VALUE}  [H_3P7]  111.82 23.67 0 top
HCPU4  VALUE}  [H_4P3X3P6]  136.15 23.67 0 top
HDD1  VALUE}  [ACES_51625-01201-001_12P]  213.65 10.25 180 bottom
HNGFF  VALUE}  [H_3P3]  189.42 26.9 0 top
JDB1  VALUE}  [ACES_51522-01001-001_10P]  43.14 70.96 90 bottom
JDEG1  VALUE}  [ACES_50521-01041-P01_10P]  24.16 60.87 270 top
JDIMM1  VALUE}  [DEREN_40-42271-26001RHF_260P-T]  77.6 86.58 270 bottom
JDIMM2  VALUE}  [DEREN_40-42261-26001RHF_260P-T]  64.9 86.58 90 bottom
JEDP  VALUE}  [ACES_51540-04001-P01_40P]  37.27 97.86 0 bottom
JFAN1  VALUE}  [ACES_50271-0040N-001_4P]  203.7 68 270 bottom
JHDMI  VALUE}  [ACON_HMRA4-AK120C_19P]  10.85 65.25 90 bottom
JHP  VALUE}  [SINGA_2SJ3095-085111F_6P-T]  12.6 6.25 270 bottom
JIO1  VALUE}  [STARC_111H40-100000-G4-R_40P]  204.88 59.66 90 bottom
JIO2  VALUE}  [ACES_50278-00401-001_4P]  209.1 13.15 0 bottom
JKB  VALUE}  [ACES_50699-03041-P01_30P]  106.3 12.62 180 bottom
JKBBL  VALUE}  [ACES_51575-00401-001_4P-T]  121.99 12.81 180 bottom
JLED  VALUE}  [ACES_50521-00641-001_6P]  66.25 11.74 180 bottom
JP1  VALUE}  [JUMP_43X79]  221.3 22.41 180 top
JP13  VALUE}  [JUMP_43X118]  197.04 43.11 0 top
JP15  VALUE}  [JUMP_43X79]  165.32 20.21 90 top
JP17  VALUE}  [JUMP_43X79]  148.05 20.3 90 top
JP21  VALUE}  [JUMP_43X118]  186.33 43.11 0 top
JRJ45  VALUE}  [SANTA_130460-3_8P]  12.15 92.28 270 top
JSPK  VALUE}  [ACES_50278-00401-001_4P]  32.3 15.45 180 bottom
JSSD1  VALUE}  [BELLW_80159-3221_67P]  217.99 21.03 270 bottom
JUSB1  VALUE}  [TAIWI_USB034-107CRL-TWD_10P-T]  11.09 51.33 90 bottom
JUSB2  VALUE}  [TAITW_PUBAUN-09FLBS1NN4H0_9P-T]  15.1 30.75 90 bottom
JWDB1  VALUE}  [CVILU_CI1804M1VRA-NH_4P]  140 17.55 0 bottom
LA1  VALUE}  [MURAT_BLM15PX221SN1D_2P]  37.15 20.84 0 top
LA3  VALUE}  [MURAT_BLM15BD601SN1D_2P]  32.6 18.34 270 top
LA4  VALUE}  [MURAT_BLM15BD601SN1D_2P]  33.81 17.83 270 top
LA5  VALUE}  [MURAT_BLM15BD601SN1D_2P]  31.46 18.34 270 top
LA6  VALUE}  [MURAT_BLM15BD601SN1D_2P]  30.32 17.83 270 top
LA7  VALUE}  [MURAT_BLM15BD601SN1D_2P]  30.55 29.36 315 top
LA8  VALUE}  [R0402_0OHM]  23.23 22.41 0 top
LA9  VALUE}  [R0402_0OHM]  23.24 21.46 0 top
LA10  VALUE}  [MURAT_BLM15BD601SN1D_2P]  32.54 28.82 270 top
NOREF  -  []  86.33 43.56 90 top
NOREF#2  -  []  148.36 102.61 0 top
NOREF#3  -  []  210.5 112.2 0 top
NOREF#4  -  []  159.41 44 0 top
NOREF#5  -  []  124.17 106.12 0 top
NOREF#6  -  []  136.15 84.67 0 top
NOREF#7  -  []  159.41 112.2 0 top
NOREF#8  -  []  26.48 100.99 0 top
NOREF#9  -  []  98.33 -34.59 0 top
NOREF#10  -  []  94.76 83.66 0 top
NOREF#11  -  []  175.99 13.46 0 top
NOREF#12  -  []  165.16 47.7 90 top
NOREF#13  -  []  91.71 67.98 90 top
NOREF#14  -  []  111.85 23.67 0 top
NOREF#15  -  []  126.8 112.2 0 top
NOREF#16  -  []  223.4 29.2 0 top
NOREF#17  -  []  89.87 41.7 0 top
NOREF#18  -  []  20.5 7.78 0 top
NOREF#19  -  []  189.42 26.9 0 top
NOREF#20  -  []  92.04 176.34 0 top
NOREF#21  -  []  150.9 107.56 180 bottom
NOREF#22  -  []  86.83 75.81 270 bottom
NOREF#23  -  []  134.73 98.15 180 bottom
PBATT1  VALUE}  [ACES_50458-01001-P01_10P-T]  174.75 29.5 180 bottom
PC1  VALUE}  [C_0402]  196.58 85.84 180 bottom
PC2  VALUE}  [C_0402]  196.57 84.89 180 bottom
PC3  VALUE}  [C_0402]  194.78 89.23 270 bottom
PC4  VALUE}  [C_0402]  195.74 89.23 270 bottom
PC7  VALUE}  [C_0402]  156.1 28.51 180 top
PC8  VALUE}  [C_0402]  155.78 31.43 90 bottom
PC14  VALUE}  [C_0402]  192.74 99.25 0 top
PC16  VALUE}  [C_0402]  198.03 98.99 180 top
PC100  VALUE}  [C_0402]  182.07 84.26 0 bottom
PC102  VALUE}  [C_0402]  177.83 77.1 270 bottom
PC103  VALUE}  [C_0402]  182.07 85.15 0 bottom
PC104  VALUE}  [C_0805]  180.03 82.93 0 bottom
PC105  VALUE}  [C_0805]  180.03 82.93 0 top
PC106  VALUE}  [C_0805]  184.73 65.46 0 bottom
PC107  VALUE}  [C_0805]  178.04 67.24 180 bottom
PC108  VALUE}  [C_0805]  184.73 67.24 0 bottom
PC109  VALUE}  [C_0805]  184.73 63.69 0 bottom
PC110  VALUE}  [C_0805]  178.04 65.46 180 bottom
PC111  VALUE}  [C_0603]  185.28 78.58 0 bottom
PC112  VALUE}  [C_0603]  181.58 81.4 0 top
PC113  VALUE}  [C_0402]  185.23 81.5 0 bottom
PC114  VALUE}  [C_0402]  189.25 76.26 0 bottom
PC115  VALUE}  [C_0402]  191.47 84.13 0 bottom
PC116  VALUE}  [C_0402]  191.47 85.02 0 bottom
PC117  VALUE}  [C_0805]  190.57 82.74 0 bottom
PC118  VALUE}  [C_0805]  190.57 82.74 0 top
PC119  VALUE}  [C_0603]  196.69 77.02 0 bottom
PC120  VALUE}  [C_0805]  196.54 65.46 0 bottom
PC121  VALUE}  [C_0805]  196.54 63.69 0 bottom
PC122  VALUE}  [C_0805]  189.98 67.24 180 bottom
PC123  VALUE}  [C_0805]  196.54 67.24 0 bottom
PC124  VALUE}  [C_0805]  189.98 65.46 180 bottom
PC125  VALUE}  [C_0603]  192.62 81.02 0 top
PC126  VALUE}  [C_0603]  196.69 78.29 0 bottom
PC127  VALUE}  [C_0402]  196.38 81.35 0 bottom
PC128  VALUE}  [C_0402]  187.61 101.35 270 top
PC200  VALUE}  [C_0402]  73.32 102.1 180 top
PC201  VALUE}  [C_0402]  79.45 104.73 0 top
PC202  VALUE}  [C_0402]  65.38 104.9 180 top
PC203  VALUE}  [C_0402]  65.36 105.81 180 top
PC204  VALUE}  [C_0603]  67.36 102.15 270 bottom
PC205  VALUE}  [C_0805]  68.41 107.73 90 bottom
PC206  VALUE}  [C_0805]  76.27 104.61 270 top
PC207  VALUE}  [C_0402]  77.24 99.02 180 bottom
PC208  VALUE}  [C_0402]  79.45 105.67 0 top
PC209  VALUE}  [C_0603]  65.31 100.71 270 bottom
PC210  VALUE}  [C_0402]  68.27 107.68 90 top
PC211  VALUE}  [C_0805]  70.18 107.73 90 bottom
PC212  VALUE}  [C_0805]  78.05 104.61 270 top
PC213  VALUE}  [C_0402]  67.25 108.58 180 top
PC214  VALUE}  [C_0402]  66.34 106.74 0 top
PC215  VALUE}  [C_0603]  86.52 99.88 270 bottom
PC216  VALUE}  [C_0603]  87.95 100.9 270 bottom
PC217  VALUE}  [C_0603]  85.18 99.88 270 bottom
PC218  VALUE}  [C_0603]  90.41 100.9 270 bottom
PC219  VALUE}  [C_0603]  89.75 107.44 0 bottom
PC220  VALUE}  [C_0603]  89.22 100.9 270 bottom
PC301  VALUE}  [C_0402]  151.88 34.02 315 top
PC302  VALUE}  [C_0402]  149.84 34.33 135 top
PC303  VALUE}  [C_0805]  149.39 31.01 270 bottom
PC304  VALUE}  [C_0402]  150.51 24.63 180 bottom
PC305  VALUE}  [C_0402]  153.98 31.41 0 bottom
PC306  VALUE}  [C_0402]  152.85 30.34 135 bottom
PC307  VALUE}  [C_0402]  149.14 32.76 180 bottom
PC308  VALUE}  [C_0603]  147.29 28.76 270 top
PC309  VALUE}  [C_0402]  151.36 23.76 90 bottom
PC310  VALUE}  [C_0603]  147.26 23.34 0 bottom
PC311  VALUE}  [C_0603]  147.26 24.61 0 bottom
PC312  VALUE}  [C_0603]  144.96 22.04 180 bottom
PC313  VALUE}  [C_0603]  144.96 23.29 180 bottom
PC501  VALUE}  [C_0603]  53.71 6.6 180 bottom
PC502  VALUE}  [C_0402]  51.05 11.22 90 bottom
PC503  VALUE}  [C_0402]  54.6 11.18 270 bottom
PC504  VALUE}  [C_0402]  50.47 6.34 0 top
PC505  VALUE}  [C_0603]  41.18 6.47 180 bottom
PC506  VALUE}  [C_0603]  41.44 11.61 180 bottom
PC507  VALUE}  [C_0603]  40.44 7.5 180 top
PC601  VALUE}  [C_0402]  157.71 69.57 270 top
PC602  VALUE}  [C_0402]  163.29 62.62 270 bottom
PC603  VALUE}  [C_0603]  164.42 64.82 90 bottom
PC604  VALUE}  [C_0603]  158.51 61.31 90 bottom
PC605  VALUE}  [C_0402]  167.8 62.62 270 bottom
PC606  VALUE}  [C_25CL33LD]  153.91 36.98 180 bottom
PC608  VALUE}  [C_0805]  154.97 49.04 270 top
PC611  VALUE}  [C_0402]  152.05 44.25 0 bottom
PC612  VALUE}  [C_0805]  154.97 48.93 270 bottom
PC613  VALUE}  [C_0402]  166.88 65.31 0 bottom
PC614  VALUE}  [C_0402]  165.51 66.28 90 bottom
PC616  VALUE}  [C_0402]  166.4 66.19 0 bottom
PC617  VALUE}  [C_0402]  170.89 67.3 0 top
PC618  VALUE}  [C_0402]  170.1 62.75 90 bottom
PC619  VALUE}  [C_0402]  169.21 62.75 90 bottom
PC620  VALUE}  [C_0402]  170.11 64.54 180 bottom
PC621  VALUE}  [C_0402]  170.08 64.61 0 top
PC622  VALUE}  [C_0603]  152.43 48.45 270 top
PC624  VALUE}  [C_0402]  169.14 67.92 90 bottom
PC625  VALUE}  [C_0402]  165.4 68.85 90 bottom
PC626  VALUE}  [C_0402]  170.03 67.92 90 bottom
PC627  VALUE}  [C_0402]  170.11 68.42 180 top
PC628  VALUE}  [C_0402]  161.57 66.8 0 bottom
PC629  VALUE}  [C_0402]  162.52 69.5 90 bottom
PC630  VALUE}  [C_0402]  160.48 71.63 180 top
PC631  VALUE}  [C_0402]  162.49 64.99 90 bottom
PC632  VALUE}  [C_0402]  159.57 65.69 180 top
PC633  VALUE}  [C_0402]  159.49 65.87 180 bottom
PC635  VALUE}  [C_0402]  170.58 70.73 0 top
PC636  VALUE}  [C_0402]  164.51 69.2 90 bottom
PC637  VALUE}  [C_0402]  159.49 64.07 180 bottom
PC638  VALUE}  [C_0402]  168.37 73.92 270 bottom
PC639  VALUE}  [C_0402]  164.93 72.07 0 top
PC640  VALUE}  [C_0402]  158.6 67.67 270 top
PC641  VALUE}  [C_0402]  171.86 68.84 270 bottom
PC642  VALUE}  [C_0402]  161.12 72.2 90 bottom
PC643  VALUE}  [C_0402]  161.57 67.69 0 bottom
PC644  VALUE}  [C_0402]  159.74 62.78 270 bottom
PC645  VALUE}  [C_0402]  160.24 72.4 180 bottom
PC646  VALUE}  [C_0402]  162.01 71.67 90 bottom
PC647  VALUE}  [C_0402]  164.93 72.96 0 top
PC649  VALUE}  [C_0402]  159.49 69.6 180 bottom
PC650  VALUE}  [C_0402]  159.49 67.71 90 bottom
PC651  VALUE}  [C_0402]  162.97 73.5 270 top
PC652  VALUE}  [C_0402]  158.6 67.71 90 bottom
PC653  VALUE}  [C_0402]  162.97 71.66 180 top
PC654  VALUE}  [C_0402]  161.38 73.45 270 top
PC655  VALUE}  [C_0402]  164.56 54.4 180 bottom
PC656  VALUE}  [C_0805]  160.52 51.11 180 bottom
PC657  VALUE}  [C_0805]  160.52 52.87 180 bottom
PC658  VALUE}  [C_0805]  160.52 51.11 180 top
PC659  VALUE}  [C_0402]  161.2 48.83 180 top
PC660  VALUE}  [C_0402]  161.2 49.72 180 top
PC661  VALUE}  [C_0402]  162.64 59.11 0 bottom
PC662  VALUE}  [C_0603]  155.67 54.22 0 top
PC663  VALUE}  [C_0402]  169.78 89.57 180 bottom
PC664  VALUE}  [C_0805]  167.31 78.04 180 bottom
PC665  VALUE}  [C_0805]  166.79 87.41 180 bottom
PC666  VALUE}  [C_0402]  167.36 78.54 180 top
PC667  VALUE}  [C_0402]  167.36 77.66 180 top
PC668  VALUE}  [C_0402]  166.79 89.72 180 top
PC669  VALUE}  [C_0402]  167.62 95.56 180 bottom
PC670  VALUE}  [C_0603]  160.15 90.93 270 top
PC671  VALUE}  [C_0402]  169.38 80.28 180 bottom
PC672  VALUE}  [C_0805]  166.79 89.12 180 bottom
PC673  VALUE}  [C_0805]  167.31 79.81 180 bottom
PC674  VALUE}  [C_0402]  166.79 87.94 180 top
PC677  VALUE}  [C_0402]  170.26 95.56 0 bottom
PC678  VALUE}  [C_0603]  161.26 80.2 0 top
PC679  VALUE}  [C_0402]  167.36 79.43 180 top
PC680  VALUE}  [C_0402]  161.2 52.45 180 top
PC681  VALUE}  [C_0402]  166.79 87.05 180 top
PC685  VALUE}  [C_0402]  148.57 41.65 180 bottom
PC686  VALUE}  [C_0402]  161.2 53.34 180 top
PC687  VALUE}  [C_0402]  166.79 88.83 180 top
PC688  VALUE}  [C_0402]  167.36 80.32 180 top
PC690  VALUE}  [C_25CL33LD]  173.64 82.26 270 bottom
PC705  VALUE}  [C_0402]  174.03 29.67 0 top
PC708  VALUE}  [C_0402]  174.69 52.59 180 top
PC711  VALUE}  [C_0402]  177.78 43.68 180 top
PC721  VALUE}  [C_0402]  169.03 47.32 0 top
PC742  VALUE}  [C_0402]  193.58 89.83 90 bottom
PC744  VALUE}  [C_0402]  192.62 89.83 90 bottom
PC747  VALUE}  [C_0402]  174.13 44.57 0 top
PC748  VALUE}  [C_0402]  180.48 48.76 0 top
PC749  VALUE}  [C_0402]  180.5 50.62 270 top
PC750  VALUE}  [C_0603]  172.88 44.25 270 top
PC751  VALUE}  [C_0402]  180.89 52.62 180 top
PC752  VALUE}  [C_0402]  180.89 53.51 180 top
PC753  VALUE}  [C_0402]  176.44 54.42 180 top
PC757  VALUE}  [C_0603]  169.08 50.36 0 top
PC760  VALUE}  [C_0603]  173.75 35.5 0 top
PC761  VALUE}  [C_0805]  158.18 27.16 270 top
PC762  VALUE}  [C_0603]  173.75 34.23 0 top
PC763  VALUE}  [C_0603]  173.75 32.96 0 top
PC764  VALUE}  [C_0603]  173.75 31.69 0 top
PC765  VALUE}  [C_0402]  174.03 30.6 0 top
PC766  VALUE}  [C_0805]  156.4 27.16 270 top
PC768  VALUE}  [C_0402]  179.54 42.97 90 top
PC769  VALUE}  [C_0402]  169.04 49.14 270 top
PC775  VALUE}  [C_0805]  154.63 27.16 270 top
PC776  VALUE}  [C_0805]  161.74 27.16 270 top
PC777  VALUE}  [C_0402]  156.1 29.48 180 top
PC778  VALUE}  [C_0805]  159.96 27.16 270 top
PC779  VALUE}  [C_0402]  154.71 32.29 0 top
PC790  VALUE}  [C_0402]  183.53 45.21 0 top
PC801  VALUE}  [C_0402]  68.42 11.95 270 bottom
PC802  VALUE}  [C_0805]  73.05 11.32 0 top
PC803  VALUE}  [C_0402]  80.2 10.41 270 top
PC804  VALUE}  [C_0805]  77.82 11.32 180 top
PC805  VALUE}  [C_0402]  73.55 9.2 0 top
PC1001  VALUE}  [C_0603]  144.75 61.27 0 top
PC1002  VALUE}  [C_0603]  151.03 65.84 0 top
PC1003  VALUE}  [C_0603]  147.92 61.27 0 bottom
PC1004  VALUE}  [C_0603]  151.03 65.84 0 bottom
PC1005  VALUE}  [C_0603]  151.03 64.32 0 top
PC1006  VALUE}  [C_0603]  151.03 62.8 0 top
PC1007  VALUE}  [C_0603]  151.03 64.32 0 bottom
PC1008  VALUE}  [C_0603]  147.92 62.8 0 bottom
PC1009  VALUE}  [C_0603]  125.99 56.88 90 top
PC1010  VALUE}  [C_0603]  124.79 56.88 90 top
PC1011  VALUE}  [C_0603]  147.92 64.32 0 bottom
PC1012  VALUE}  [C_0603]  151.03 62.8 0 bottom
PC1013  VALUE}  [C_0603]  151.03 61.27 0 bottom
PC1014  VALUE}  [C_0603]  128.89 66.65 270 top
PC1015  VALUE}  [C_0603]  126.48 66.65 270 top
PC1016  VALUE}  [C_0603]  122.86 64.26 270 top
PC1017  VALUE}  [C_0603]  121.65 64.26 270 top
PC1018  VALUE}  [C_0603]  127.68 64.26 270 top
PC1019  VALUE}  [C_0603]  128.89 64.26 270 top
PC1020  VALUE}  [C_0603]  128.89 61.91 270 top
PC1021  VALUE}  [C_0603]  125.7 77.02 180 top
PC1022  VALUE}  [C_0603]  151.16 93.21 90 top
PC1023  VALUE}  [C_0603]  125.7 80.83 180 bottom
PC1024  VALUE}  [C_0603]  149.51 93.21 90 bottom
PC1025  VALUE}  [C_0603]  149.51 93.21 90 top
PC1026  VALUE}  [C_0603]  151.16 90.67 90 top
PC1027  VALUE}  [C_0603]  149.51 90.67 90 top
PC1028  VALUE}  [C_0603]  149.51 88.13 90 top
PC1029  VALUE}  [C_0603]  127.68 66.65 270 top
PC1030  VALUE}  [C_0201]  122.69 53.5 90 top
PC1031  VALUE}  [C_0201]  120.44 58.41 270 top
PC1032  VALUE}  [C_0201]  126.86 50.73 0 top
PC1033  VALUE}  [C_0201]  119.87 58.41 270 top
PC1034  VALUE}  [C_0201]  122.69 56.79 90 top
PC1035  VALUE}  [C_0201]  129.11 50.73 180 top
PC1036  VALUE}  [C_0201]  129.11 51.3 180 top
PC1037  VALUE}  [C_0201]  123.42 51.28 180 top
PC1038  VALUE}  [C_0201]  121.53 52.43 270 top
PC1039  VALUE}  [C_0201]  121.11 50.67 0 top
PC1040  VALUE}  [C_0201]  120.8 65 180 top
PC1041  VALUE}  [C_0201]  122.67 59.15 90 top
PC1042  VALUE}  [C_0201]  123.12 66.85 270 top
PC1043  VALUE}  [C_0201]  123.23 59.15 90 top
PC1044  VALUE}  [C_0201]  120.16 63.56 0 top
PC1045  VALUE}  [C_0201]  121.83 65.03 0 top
PC1046  VALUE}  [C_0201]  121.83 65.64 0 top
PC1047  VALUE}  [C_0201]  121.28 66.25 0 top
PC1048  VALUE}  [C_0201]  129.18 59.15 180 top
PC1049  VALUE}  [C_0201]  129.18 59.73 180 top
PC1050  VALUE}  [C_0201]  122.67 58.55 270 top
PC1051  VALUE}  [C_0201]  124.03 51.28 0 top
PC1052  VALUE}  [C_0201]  122.67 52.43 270 top
PC1053  VALUE}  [C_0201]  122.1 52.43 270 top
PC1054  VALUE}  [C_0201]  121.57 55.72 270 top
PC1055  VALUE}  [C_0201]  123.79 59.15 90 top
PC1056  VALUE}  [C_0201]  124.35 59.15 90 top
PC1057  VALUE}  [C_0603]  127.87 48.55 90 top
PC1058  VALUE}  [C_0603]  123.05 48.55 90 top
PC1059  VALUE}  [C_0603]  141.89 49.08 90 bottom
PC1060  VALUE}  [C_0603]  141.89 46.86 270 bottom
PC1061  VALUE}  [C_0603]  147.92 64.32 0 top
PC1062  VALUE}  [C_D2]  146.08 68.61 90 bottom
PC1063  VALUE}  [C_D2]  144.05 85.55 270 bottom
PC1064  VALUE}  [C_0603]  127.2 52.07 90 top
PC1065  VALUE}  [C_0603]  125.99 52.07 90 top
PC1066  VALUE}  [C_0603]  124.79 55.84 270 top
PC1067  VALUE}  [C_0603]  123.58 55.84 270 top
PC1068  VALUE}  [C_0603]  128.41 52.07 90 top
PC1069  VALUE}  [C_0603]  124.79 52.05 90 top
PC1070  VALUE}  [C_0603]  125.99 55.84 270 top
PC1071  VALUE}  [C_0603]  144.75 64.32 0 top
PC1072  VALUE}  [C_0603]  147.92 65.84 0 bottom
PC1073  VALUE}  [C_0603]  128.41 56.89 90 top
PC1074  VALUE}  [C_0603]  144.75 65.84 0 bottom
PC1075  VALUE}  [C_0603]  144.75 64.32 0 bottom
PC1076  VALUE}  [C_0603]  144.75 65.84 0 top
PC1077  VALUE}  [C_0603]  123.58 52.05 90 top
PC1078  VALUE}  [C_0603]  128.41 55.85 270 top
PC1079  VALUE}  [C_0603]  127.2 55.84 270 top
PC1080  VALUE}  [C_0603]  123.58 56.88 90 top
PC1081  VALUE}  [C_0603]  144.75 62.8 0 top
PC1082  VALUE}  [C_0603]  147.92 65.84 0 top
PC1083  VALUE}  [C_0201]  122.69 55.72 270 top
PC1084  VALUE}  [C_0201]  122.13 53.5 90 top
PC1085  VALUE}  [C_0201]  122.13 55.72 270 top
PC1086  VALUE}  [C_0201]  121.56 58.55 270 top
PC1087  VALUE}  [C_0201]  121 58.55 270 top
PC1088  VALUE}  [C_0201]  119.36 52.83 0 top
PC1089  VALUE}  [C_0201]  121.57 56.79 90 top
PC1090  VALUE}  [C_0201]  122.11 58.55 270 top
PC1091  VALUE}  [C_0201]  121.01 56.79 90 top
PC1092  VALUE}  [C_0201]  121.57 53.5 90 top
PC1093  VALUE}  [C_0201]  126.28 50.73 180 top
PC1094  VALUE}  [C_0201]  124.03 50.72 0 top
PC1095  VALUE}  [C_0201]  123.42 50.72 180 top
PC1096  VALUE}  [C_0201]  119.35 53.4 0 top
PC1097  VALUE}  [C_0201]  122.13 56.79 90 top
PC1098  VALUE}  [C_0201]  126.86 51.3 0 top
PC1099  VALUE}  [C_0201]  126.28 51.3 180 top
PC1101  VALUE}  [C_D2]  120.32 95.44 180 bottom
PC1125  VALUE}  [C_0201]  118.69 54.81 180 top
PC1126  VALUE}  [C_0201]  121.11 51.24 0 top
PC1127  VALUE}  [C_D2]  151.67 68.61 90 bottom
PC1128  VALUE}  [C_D2]  149.63 85.55 270 bottom
PC1129  VALUE}  [C_0603]  126.48 61.91 270 top
PC1130  VALUE}  [C_0603]  125.27 61.91 270 top
PC1131  VALUE}  [C_0603]  125.7 79.56 180 top
PC1132  VALUE}  [C_0603]  125.7 79.56 180 bottom
PC1133  VALUE}  [C_0603]  128.62 77.02 180 top
PC1134  VALUE}  [C_0603]  128.62 78.29 180 bottom
PC1135  VALUE}  [C_0603]  125.7 80.83 180 top
PC1136  VALUE}  [C_0603]  121.65 61.91 270 top
PC1137  VALUE}  [C_0603]  122.86 61.91 270 top
PC1138  VALUE}  [C_0603]  124.06 61.91 270 top
PC1139  VALUE}  [C_0603]  124.25 48.55 90 top
PC1140  VALUE}  [C_0603]  126.67 48.55 90 top
PC1141  VALUE}  [C_0603]  144.17 46.86 270 top
PC1142  VALUE}  [C_0603]  129.08 48.55 90 top
PC1143  VALUE}  [C_0603]  144.17 49.08 90 top
PC1144  VALUE}  [C_0603]  142.9 49.08 90 top
PC1145  VALUE}  [C_0603]  142.9 46.86 270 top
PC1146  VALUE}  [C_0603]  125.46 48.55 90 top
PC1147  VALUE}  [C_0201]  125.78 47.71 270 top
PC1148  VALUE}  [C_0201]  121.58 49.23 90 top
PC1149  VALUE}  [C_0201]  121.82 48.04 270 top
PC1150  VALUE}  [C_0201]  122.15 49.23 90 top
PC1151  VALUE}  [C_0201]  121.25 48.61 270 top
PC1152  VALUE}  [C_0201]  122.63 47.79 0 top
PC1153  VALUE}  [C_0201]  121 49.23 90 top
PC1154  VALUE}  [C_0603]  125.7 78.29 180 bottom
PC1155  VALUE}  [C_0603]  128.62 80.83 180 bottom
PC1156  VALUE}  [C_0603]  125.7 78.29 180 top
PC1158  VALUE}  [C_0603]  128.62 82.1 180 bottom
PC1159  VALUE}  [C_0603]  128.62 75.75 180 top
PC1161  VALUE}  [C_0603]  149.51 88.13 90 bottom
PC1162  VALUE}  [C_0603]  128.62 80.83 180 top
PC1163  VALUE}  [C_0603]  149.51 90.67 90 bottom
PC1164  VALUE}  [C_0201]  119.92 54.69 90 top
PC1170  VALUE}  [C_0603]  127.2 56.88 90 top
PC1171  VALUE}  [C_0603]  144.75 61.27 0 bottom
PC1172  VALUE}  [C_0603]  144.75 62.8 0 bottom
PC1173  VALUE}  [C_0603]  147.92 62.8 0 top
PC1174  VALUE}  [C_0603]  147.92 61.27 0 top
PC1175  VALUE}  [C_0603]  125.27 66.65 270 top
PC1176  VALUE}  [C_0603]  124.06 66.65 270 top
PC1177  VALUE}  [C_0603]  124.06 64.26 270 top
PC1178  VALUE}  [C_0603]  126.48 64.26 270 top
PC1179  VALUE}  [C_0603]  125.27 64.26 270 top
PC1180  VALUE}  [C_0603]  127.68 61.91 270 top
PC1181  VALUE}  [C_0603]  125.7 82.1 180 bottom
PC1182  VALUE}  [C_0603]  128.62 79.56 180 bottom
PC1183  VALUE}  [C_0603]  125.7 75.75 180 top
PC1184  VALUE}  [C_0603]  128.62 78.29 180 top
PC1201  VALUE}  [C_0402]  110.15 101.98 90 bottom
PC1202  VALUE}  [C_0402]  102.57 109.34 90 bottom
PC1203  VALUE}  [C_0603]  101.45 109.34 90 bottom
PC1204  VALUE}  [C_0402]  106.57 110.42 0 bottom
PC1205  VALUE}  [C_0402]  107.95 103.44 180 bottom
PC1206  VALUE}  [C_0603]  116.23 103.69 270 bottom
PC1207  VALUE}  [C_0603]  118.77 103.69 270 bottom
PC1208  VALUE}  [C_0603]  117.5 103.69 270 bottom
PC1209  VALUE}  [C_0402]  115.29 109.92 90 bottom
PC1221  VALUE}  [C_0603]  128.62 79.56 180 top
PC1222  VALUE}  [C_0603]  151.16 93.21 90 bottom
PC1223  VALUE}  [C_0603]  151.16 90.67 90 bottom
PC1224  VALUE}  [C_0603]  151.16 88.13 90 bottom
PD2  VALUE}  [TVNST52302AB0_SOT523-3]  164.26 24.09 180 top
PD3  VALUE}  [TVNST52302AB0_SOT523-3]  168.65 25.41 270 top
PD4  VALUE}  [TVNST52302AB0_SOT523-3]  202.34 82.61 270 top
PD5  VALUE}  [BAV99W_SC70-3]  208.73 80.45 270 top
PD6  VALUE}  [BAV99W_SC70-3]  203.96 79.18 90 top
PD102  VALUE}  [SDMK0340L-7-F_SOD323-2]  190.4 102.87 180 top
PD704  VALUE}  [LRB715FT1G_SOT323-3]  170.72 59.81 270 top
PH601  VALUE}  [R_0402]  161.75 79.94 0 bottom
PH602  VALUE}  [R_0402]  160.76 78.67 180 bottom
PH603  VALUE}  [R_0402]  157.33 59.19 180 bottom
PH604  VALUE}  [R_0402]  145.69 44.51 0 bottom
PH605  VALUE}  [R_0402]  153.88 60.26 0 bottom
PJP3  VALUE}  [JUMP_43X79]  158.46 30.36 270 top
PJP102  VALUE}  [JUMP_43X118]  181.26 65.72 270 bottom
PJP103  VALUE}  [JUMP_43X118]  193.2 65.63 270 bottom
PJP105  VALUE}  [JUMP_43X79]  179.67 86.46 270 bottom
PJP106  VALUE}  [JUMP_43X79]  189.13 86.21 270 bottom
PJP200  VALUE}  [JUMP_43X118]  89.9 104.14 0 bottom
PJP203  VALUE}  [JUMP_43X79]  73.32 107.48 180 bottom
PJP206  VALUE}  [JUMP_43X79]  77.42 107.36 90 top
PJP301  VALUE}  [JUMP_43X39]  152.21 36.47 270 top
PJP302  VALUE}  [JUMP_43X118]  148.11 21.4 270 bottom
PJP501  VALUE}  [JUMP_43X79]  55.41 7.94 180 top
PJP502  VALUE}  [JUMP_43X79]  40.57 9.02 180 bottom
PJP601  VALUE}  [JUMP_43X118]  164.87 49.63 270 bottom
PJP602  VALUE}  [JUMP_43X118]  174.87 87.05 0 bottom
PJP603  VALUE}  [JUMP_43X39]  156.54 49.28 0 bottom
PJP701  VALUE}  [JUMP_43X118]  165.84 37.32 0 bottom
PJP801  VALUE}  [JUMP_43X79]  70.22 10.35 0 top
PJP802  VALUE}  [JUMP_43X79]  81.84 10.85 0 top
PJP1201  VALUE}  [JUMP_43X79]  101.94 106.37 0 bottom
PJP1202  VALUE}  [JUMP_43X79]  117.89 106.21 0 bottom
PJPDC1  VALUE}  [ACES_50458-00601-001_6P-T]  202.3 90.2 270 bottom
PL1  VALUE}  [5A_Z150_1210_2P]  198.12 87.1 90 bottom
PL2  VALUE}  [MURAT_BLM15AG102SN1D_2P]  201.81 85.4 180 top
PL4  VALUE}  [5A_Z150_1210_2P]  201.79 93.15 180 bottom
PL100  VALUE}  [L_7X7X3_M_2P]  181.26 74.97 270 bottom
PL101  VALUE}  [L_7X7X3_M_2P]  193.13 74.97 270 bottom
PL102  VALUE}  [5A_Z150_1210_2P-NPM]  179.67 87.26 270 bottom
PL103  VALUE}  [5A_Z150_1210_2P-NPM]  189.13 87.01 270 bottom
PL200  VALUE}  [L_7X7X3_M_2P]  86.53 104.14 180 bottom
PL301  VALUE}  [L_5X5X3_M_2P]  145.57 31.44 270 bottom
PL501  VALUE}  [L_5X5X3_M_2P]  47.92 8.81 180 bottom
PL601  VALUE}  [L_5X5X3_M]  144.43 47.94 0 bottom
PL603  VALUE}  [L_7X7X4_M]  148.49 55.94 0 bottom
PL604  VALUE}  [L_7X7X4_M]  154.48 91.24 0 bottom
PL605  VALUE}  [L_7X7X4_M]  154.48 82.99 0 bottom
PL606  VALUE}  [5A_Z150_1210_2P-NPM]  174.07 87.05 0 bottom
PL700  VALUE}  [L_7X7X3_M_2P]  174.54 39.27 270 bottom
PL704  VALUE}  [L_5X5X3_M_2P-NPM]  164.21 37.32 0 bottom
PL1201  VALUE}  [L_5X5X3_M_2P]  110.52 106.36 0 bottom
PQ1  VALUE}  [2N7002DW-T-R7_SOT363-6]  200 99.9 0 top
PQ2  VALUE}  [2N7002DW-T-R7_SOT363-6]  196.56 100.47 0 top
PQ3  VALUE}  [L2N7002WT1G_SC70-3]  194.34 102.35 180 top
PQ5  VALUE}  [RHU002N06_SOT323-3]  199.04 81.3 0 top
PQ6  VALUE}  [FDV301N_NL_SOT23-3]  203.71 84.39 270 top
PQ102  VALUE}  [L2N7002WT1G_SC70-3]  188.27 105.05 270 top
PQ201  VALUE}  [AON7934_DFN3X3A8-10]  75.8 105.64 0 bottom
PQ601  VALUE}  [AON7934_DFN3X3A8-10]  151.41 50.1 0 bottom
PQ704  VALUE}  [SIS412DN-T1-GE3_POWERPAK8-5]  172.01 38.17 180 top
PQ708  VALUE}  [SIS412DN-T1-GE3_POWERPAK8-5]  176.85 37.14 90 top
PQ709  VALUE}  [2N7002DW-T-R7_SOT363-6]  183.85 100.4 0 top
PQ710  VALUE}  [LMUN5113T1G_SOT323-3]  174.02 60.38 270 top
PQ711  VALUE}  [LTC015EUBFS8TL_UMT3F]  174.23 57.84 90 top
PQ717  VALUE}  [MDU1512RH_POWERDFN56-8-5]  161.07 33 180 bottom
PQ718  VALUE}  [MDU1512RH_POWERDFN56-8-5]  190.15 94.13 270 bottom
PQ720  VALUE}  [RUM002N02GT2L_VMT3]  182.53 47.37 270 top
PQ721  VALUE}  [RUM002N02GT2L_VMT3]  181.32 45.59 90 top
PQ740  VALUE}  [SIS412DN-T1-GE3_POWERPAK8-5]  192.95 92.22 90 bottom
PQ741  VALUE}  [MDU1512RH_POWERDFN56-8-5]  191.09 93.5 180 top
PR2  VALUE}  [R_0402]  199.23 98.05 270 top
PR3  VALUE}  [R_0402]  207.67 83.83 270 top
PR4  VALUE}  [R_0402]  207.67 85.61 270 top
PR5  VALUE}  [R_1206]  202.91 102.36 270 top
PR6  VALUE}  [R_0402]  200.93 84.39 0 top
PR7  VALUE}  [R_0402]  196.32 104.77 180 top
PR8  VALUE}  [R_0402]  205.77 81.01 90 top
PR9  VALUE}  [R_0402]  198.83 84.39 0 top
PR10  VALUE}  [R_0402]  201.34 103.12 180 top
PR11  VALUE}  [R_0402]  204.88 81.92 270 top
PR12  VALUE}  [R_0402]  201.01 97.14 90 top
PR13  VALUE}  [R_0402]  200.12 97.14 90 top
PR15  VALUE}  [R_0402]  165.94 27.67 270 top
PR16  VALUE}  [R_0402]  165.94 25.56 270 top
PR18  VALUE}  [R_0402]  164.89 27.67 270 top
PR20  VALUE}  [R_0402]  163.72 27.66 270 top
PR28  VALUE}  [R_0402]  198.02 97.14 90 top
PR29  VALUE}  [R_0402]  197.13 98.05 270 top
PR31  VALUE}  [R_0402]  196.32 103.82 180 top
